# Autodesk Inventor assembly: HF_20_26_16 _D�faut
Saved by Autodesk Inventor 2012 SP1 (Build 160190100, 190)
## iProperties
Created: 2011-01
Part Number: HF_20_26_16 _D�faut
Document SubType Name: Assembly
Designer: eric
Mass: 2.78295 g
Surface Area: 53.1486 cm^2
Volume: 2.78295 cm^3
Density: 1 g/cm^3
Author: eric
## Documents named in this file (3)
- D:\Cours\Inventor salle SI\chariot_de_golf_2008\chariot_de_golf_trolem\HF_20_26_16 _Defaut.iam
- D:\Cours\Inventor salle SI\chariot_de_golf_2008\chariot_de_golf_trolem\aiguilles_HF20_26_16_Defaut.ipt
- D:\Cours\Inventor salle SI\chariot_de_golf_2008\chariot_de_golf_trolem\cage_HF20_26_16_Defaut.ipt
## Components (25 placed, 2 different names)
1. aiguilles_HF20_26_16_Defaut:1
2. aiguilles_HF20_26_16_Defaut:2
3. aiguilles_HF20_26_16_Defaut:3
4. aiguilles_HF20_26_16_Defaut:4
5. aiguilles_HF20_26_16_Defaut:5
6. cage_HF20_26_16_Defaut:1
7. aiguilles_HF20_26_16_Defaut:6
8. aiguilles_HF20_26_16_Defaut:7
9. aiguilles_HF20_26_16_Defaut:8
10. aiguilles_HF20_26_16_Defaut:9
11. aiguilles_HF20_26_16_Defaut:10
12. aiguilles_HF20_26_16_Defaut:11
13. aiguilles_HF20_26_16_Defaut:12
14. aiguilles_HF20_26_16_Defaut:13
15. aiguilles_HF20_26_16_Defaut:14
16. aiguilles_HF20_26_16_Defaut:15
17. aiguilles_HF20_26_16_Defaut:16
18. aiguilles_HF20_26_16_Defaut:17
19. aiguilles_HF20_26_16_Defaut:18
20. aiguilles_HF20_26_16_Defaut:19
21. aiguilles_HF20_26_16_Defaut:20
22. aiguilles_HF20_26_16_Defaut:21
23. aiguilles_HF20_26_16_Defaut:22
24. aiguilles_HF20_26_16_Defaut:23
25. aiguilles_HF20_26_16_Defaut:24
